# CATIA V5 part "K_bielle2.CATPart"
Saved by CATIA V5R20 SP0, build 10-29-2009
Part number: bielle2
Bounding box of the stored display mesh (mm): x -20 to 20, y 160.846 to 197.306, z 146.113 to 175.633
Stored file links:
  G:\Khaled_CFAO_2011\ST2M\ST2M_GR1\hgrenier\Khaled\CAD_ThinkMOTION\K_bielle2.CATPart
  C:\Users\Tom\Documents\Cours 2A\CFAO\Projet thinkmotion\Hugo\porte_outil.CATProduct
  G:\Khaled_CFAO_2011\ST2M\ST2M_GR1\hgrenier\Khaled\CAD_ThinkMOTION\K_Bras.CATPart
  G:\Khaled_CFAO_2011\ST2M\ST2M_GR1\hgrenier\Khaled\CAD_ThinkMOTION\K_TigeVerin1.CATPart
  G:\Khaled_CFAO_2011\ST2M\ST2M_GR1\hgrenier\Khaled\CAD_ThinkMOTION\K_Bielette.CATPart
  G:\Khaled_CFAO_2011\ST2M\ST2M_GR1\hgrenier\Khaled\CAD_ThinkMOTION\K_Godet.CATPart
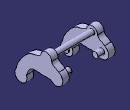
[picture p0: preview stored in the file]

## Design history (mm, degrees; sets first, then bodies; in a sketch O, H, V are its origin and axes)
External parameters (linked from other documents)
  External.diametre_trou_bielle2 = 4.78 mm
  `External.diametre_trou_bielle2/verin1` = 4 mm
  External.Rayon = 2.1195 mm
  External.Longueur = 5 mm
Set1
  Plane1 "Plan_bielle2": linked copy from another document
  Point1 "Centre_verin/bielle2": linked copy from another document
  Point2 "Centre_bielle2/bielette": linked copy from another document
  Point3 "Centre_bras/bielle2": linked copy from another document
  Plane2 "Plan_godet": linked copy from another document
  Plane3 "plan_sym": linked copy from another document
  DatumSurface1: linked copy from another document
Body1 (main body)
  Sketch1 on Plane1, origin (15, 0, 0), H (0, 1, 0), V (0, 0, 1)
    arc A1 centre (192.173, 162.375) radius 5.1357 from (188.2573, 159.0519) to (194.3024, 167.0484) ccw
    point P1 (192.173, 162.375)
    arc A2 centre (165.417, 150.684) radius 4.5709 from (161.7297, 153.3853) to (169.4662, 152.8046) ccw
    point P2 (165.417, 150.684)
    arc A3 centre (184.816, 171.511) radius 4.1252 from (188.9408, 171.5693) to (180.7095, 171.9038) ccw
    point P3 (184.816, 171.511)
    reference projected point E1 (184.816, 171.511) from Point1
    reference projected point E2 (192.173, 162.375) from Point2
    reference projected point E3 (165.417, 150.684) from Point3
    spline S1 through (161.7297, 153.3853) (164.3103, 159.8321) (168.2455, 165.1268) (174.691, 169.3354) (179.2368, 170.6931) (180.7095, 171.9038)
    spline S2 through (169.4662, 152.8046) (171.0951, 156.2345) (172.6556, 158.3388) (175.5052, 159.4249) (179.7795, 159.2891) (183.579, 159.2212) (188.2573, 159.0519)
    spline S3 through (194.3024, 167.0484) (191.5171, 168.7924) (189.7531, 169.8785) (188.9408, 171.5693)
    point P4 (194.3024, 167.0484)
    point P5 (188.2573, 159.0519)
    point P6 (188.9408, 171.5693)
    point P7 (180.7095, 171.9038)
    point P8 (169.4662, 152.8046)
    point P9 (161.7297, 153.3853)
    point P10 (161.7297, 153.3853)
    point P11 (180.7095, 171.9038)
    point P12 (169.4662, 152.8046)
    point P13 (188.2573, 159.0519)
    point P14 (194.3024, 167.0484)
    point P15 (188.9408, 171.5693)
    coincidence: P3 E1, P1 E2, P2 E3, P10 A2, P11 A3, P12 A2, P13 A1, P14 A1, P15 A3, P14 P4, P13 P5, P11 P7, S3 P6, P12 P8, P10 P9, P15 P6
  Pad1: profile Sketch1, direction (1, 0, 0), length 5
  Sketch2 on start face of Pad1, origin (15, 0, 0), H (0, -1, 0), V (0, 0, 1)
    circle A1 centre (-165.417, 150.684) radius 2.39
    point P1 (-165.417, 150.684)
    reference projected point E1 (-165.417, 150.684) from Point3
    radius A1 = 2.39 {= External.diametre_trou_bielle2 /2}
    coincidence: P1 E1
  Pad2: profile Sketch2, direction (-1, 0, 0), length 1
  Sketch3 on start face of Pad1, origin (15, 0, 0), H (0, -1, 0), V (0, 0, 1)
    circle A1 centre (-184.816, 171.511) radius 2
    point P1 (-184.816, 171.511)
    reference projected point E1 (-184.816, 171.511) from Point1
    radius A1 = 2 {= `External.diametre_trou_bielle2/verin1` /2}
    coincidence: P1 E1
  Pad3: profile Sketch3, direction (-1, 0, 0), up to Plane3
  Sketch4 on start face of Pad1, origin (15, 0, 0), H (0, -1, 0), V (0, 0, 1)
    circle A1 centre (-192.173, 162.375) radius 2.1195
    point P1 (-192.173, 162.375)
    reference projected point E1 (-192.173, 162.375) from Point2
    radius A1 = 2.1195 {= External.Rayon}
    coincidence: P1 E1
  Pad4: profile Sketch4, direction (-1, 0, 0), length 5 {= External.Longueur}
  Mirror1: of the body so far, about Plane3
